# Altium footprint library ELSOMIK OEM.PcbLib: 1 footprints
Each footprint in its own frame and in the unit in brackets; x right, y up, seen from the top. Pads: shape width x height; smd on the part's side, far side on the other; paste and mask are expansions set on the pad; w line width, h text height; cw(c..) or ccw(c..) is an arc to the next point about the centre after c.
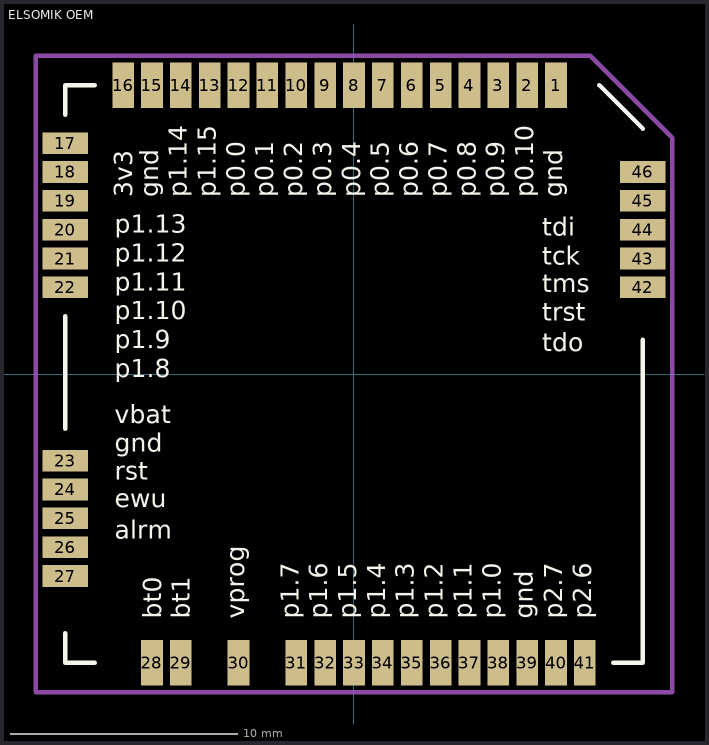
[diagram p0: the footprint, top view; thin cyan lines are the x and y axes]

## ELSOMIK OEM [mm] "Модуль SOM (System on module) с микроконтроллером 1-го уровня MIK32 АМУР (к1948вк018) - ELSOMIK OEM"
pads (46):
  rect 0.95x2 smd paste-2539.97: 1(8.89,12.7) 2(7.62,12.7) 3(6.35,12.7) 4(5.08,12.7) 5(3.81,12.7) 6(2.54,12.7) 7(1.27,12.7) 8(0,12.7) 9(-1.27,12.7) 10(-2.54,12.7) 11(-3.81,12.7) 12(-5.08,12.7) 13(-6.35,12.7) 14(-7.62,12.7) 15(-8.89,12.7) 16(-10.16,12.7) 28(-8.89,-12.7) 29(-7.62,-12.7) 30(-5.08,-12.7) 31(-2.54,-12.7) 32(-1.27,-12.7) 33(0,-12.7) 34(1.27,-12.7) 35(2.54,-12.7) 36(3.81,-12.7) 37(5.08,-12.7) 38(6.35,-12.7) 39(7.62,-12.7) 40(8.89,-12.7) 41(10.16,-12.7)
  rect 2x0.95 smd paste-2539.97: 17(-12.7,10.16) 18(-12.7,8.89) 19(-12.7,7.62) 20(-12.7,6.35) 21(-12.7,5.08) 22(-12.7,3.81) 23(-12.7,-3.81) 24(-12.7,-5.08) 25(-12.7,-6.35) 26(-12.7,-7.62) 27(-12.7,-8.89) 42(12.7,3.81) 43(12.7,5.08) 44(12.7,6.35) 45(12.7,7.62) 46(12.7,8.89)
Top Overlay:
  lines w0.2: -12.7,-11.4 -12.7,-12.7 -11.4,-12.7 ; -12.7,-2.413 -12.7,2.54 ; -12.7,11.4 -12.7,12.7 -11.4,12.7 ; 10.8,12.7 12.7,10.8 ; 11.4,-12.7 12.7,-12.7 12.7,-11.4 12.7,1.5
  text "p1.9" at -10.518,1.131 h0.8
  text "p1.8" at -10.518,-0.139 h0.8
  text "p1.11" at -10.518,3.671 h0.8
  text "p1.12" at -10.518,4.941 h0.8
  text "p1.13" at -10.518,6.211 h0.8
  text "p1.10" at -10.518,2.401 h0.8
  text "vprog" at -4.82,-10.772 h0.8
  text "p1.1" at 5.179,-10.772 h0.8
  text "p1.2" at 3.909,-10.772 h0.8
  text "p1.6" at -1.171,-10.772 h0.8
  text "p1.5" at 0.099,-10.772 h0.8
  text "p1.4" at 1.369,-10.772 h0.8
  text "p1.3" at 2.639,-10.772 h0.8
  text "p1.7" at -2.441,-10.772 h0.8
  text "p0.8" at 5.347,7.77 h0.8
  text "p0.7" at 4.077,7.77 h0.8
  text "p0.6" at 2.807,7.77 h0.8
  text "p0.5" at 1.537,7.77 h0.8
  text "p0.4" at 0.267,7.77 h0.8
  text "p0.3" at -1.003,7.77 h0.8
  text "p0.2" at -2.273,7.77 h0.8
  text "p0.1" at -3.543,7.77 h0.8
  text "p0.0" at -4.813,7.77 h0.8
  text "p1.15" at -6.083,7.77 h0.8
  text "p1.14" at -7.353,7.77 h0.8
  text "gnd" at -8.623,7.77 h0.8
  text "3v3" at -9.76,7.77 h0.8
  text "gnd" at 9.157,7.77 h0.8
  text "tdi" at 8.278,6.077 h0.8
  text "tck" at 8.278,4.807 h0.8
  text "tms" at 8.278,3.604 h0.8
  text "tdo" at 8.278,0.997 h0.8
  text "trst" at 8.278,2.334 h0.8
  text "p0.10" at 7.887,7.77 h0.8
  text "p0.9" at 6.617,7.77 h0.8
  text "gnd" at 7.857,-10.772 h0.8
  text "p1.0" at 6.449,-10.772 h0.8
  text "p2.7" at 9.174,-10.772 h0.8
  text "p2.6" at 10.444,-10.772 h0.8
  text "bt0" at -8.49,-10.772 h0.8
  text "rst" at -10.518,-4.651 h0.8
  text "vbat" at -10.518,-2.178 h0.8
  text "ewu" at -10.518,-5.854 h0.8
  text "alrm" at -10.518,-7.258 h0.8
  text "bt1" at -7.22,-10.772 h0.8
  text "gnd" at -10.518,-3.413 h0.8
Mechanical 15:
  lines w0.2: -14,-14 14,-14 14,10.4 10.4,14 -10.7,14 -14,14 -14,-14
3D body "3D ELSOMIK OEM.step": height 1.77, standoff 0, extent -12.7,-12.7 12.7,12.7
